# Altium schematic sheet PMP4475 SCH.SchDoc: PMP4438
size A4; VersionControl_RevNumber: A; Date: 2012-12-10; ApprovedBy: Xiaoguang Yu; CheckedBy: David Ji; Author: David Ji; CompanyName: Texas Instruments; DrawnBy: David Ji; Engineer: David Ji; Organization: Power Reference Design; Address1: Texas Instruments; Address2: Power Reference Design; Address3: PMP4438; Address4: Not shown in title block; DocumentNumber: 1; Revision: Rev. A; SheetNumber: 1; SheetTotal: 1; PageSetup: Record=PageOptions¦CenterHorizontal=True¦CenterVertical=True¦PrintScale=0.97¦XCorrection=1.00¦YCorrection=1.00¦PrintKind=0¦BorderSize=5000000¦LeftOffset=0¦BottomOffset=0¦Orientation=2¦PaperLength=1000¦PaperWidth=1000¦Scale=100¦PaperSource=15¦PrintQuality=600¦MediaType=1¦DitherType=10¦PaperKind=Letter¦PrintScaleMode=1
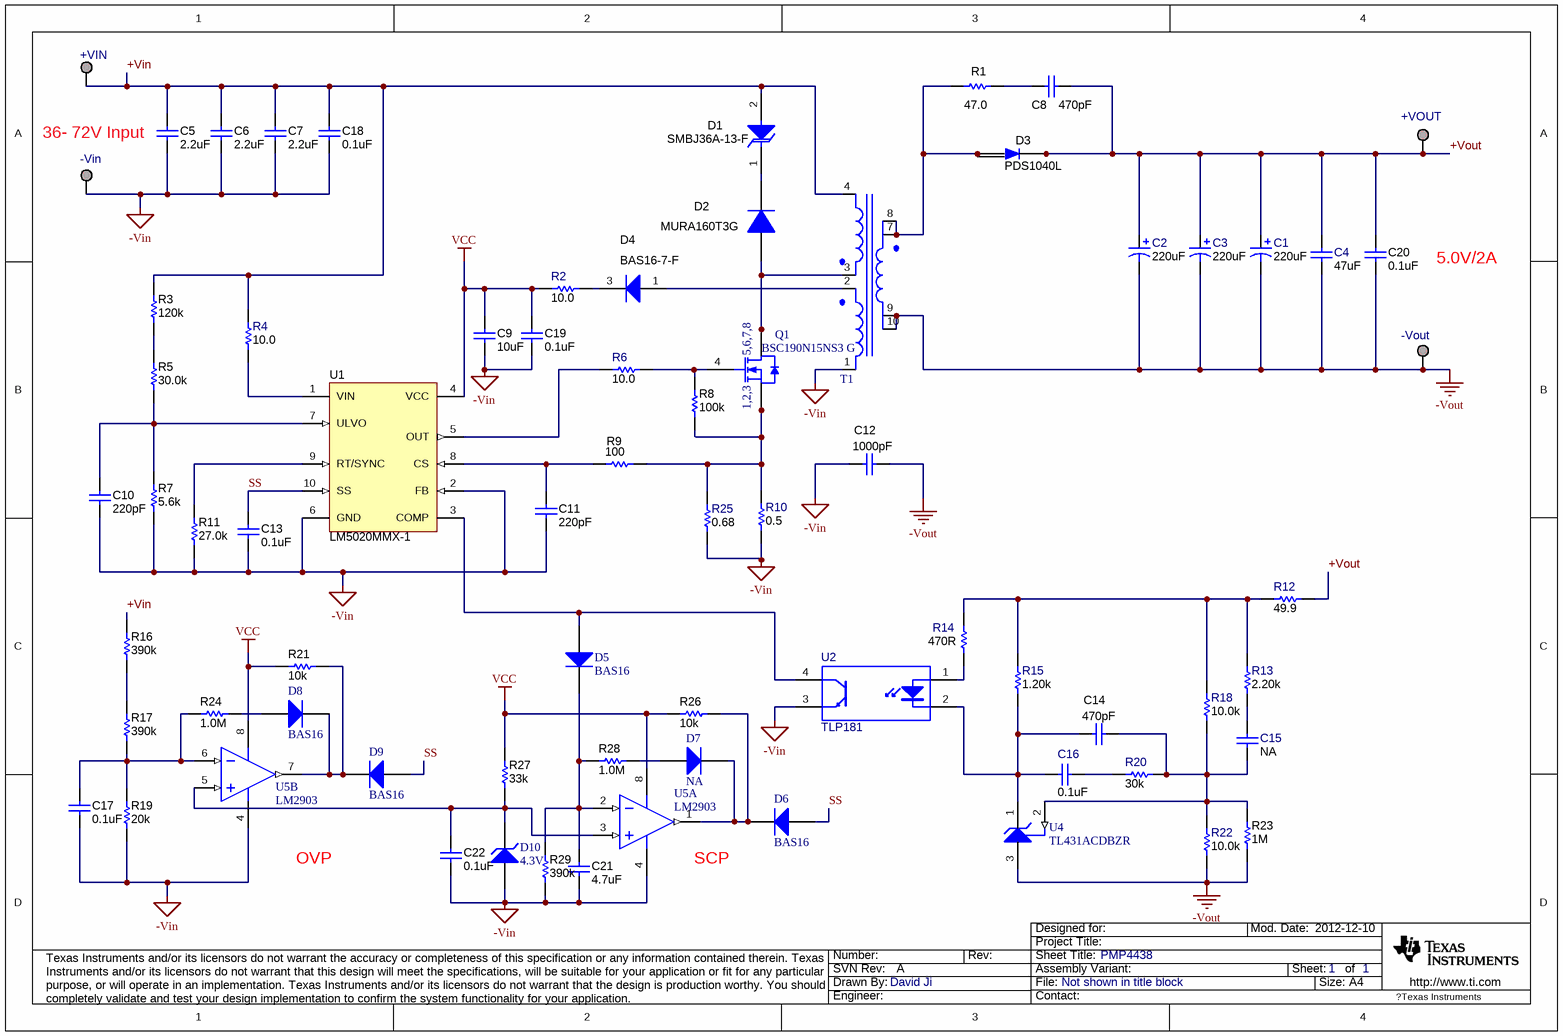
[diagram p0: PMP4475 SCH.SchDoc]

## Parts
+VIN  TESTPOINT  [Copper PIN-1.0]  (value not drawn)  (no BOM)
+VOUT  TESTPOINT  [Copper PIN-1.0]  (value not drawn)  (no BOM)
-Vin  TESTPOINT  [Copper PIN-1.0]  (value not drawn)  (no BOM)
-Vout  TESTPOINT  [Copper PIN-1.0]  (value not drawn)  (no BOM)
C1  ValueDisplayed: 220uF  [POSCAP B2E Size]  (hidden comment: 6TPE150MAPB)
C2  ValueDisplayed: 220uF  [POSCAP B2E Size]  (hidden comment: 6TPE150MAPB)
C3  ValueDisplayed: 220uF  [POSCAP B2E Size]  (hidden comment: 6TPE150MAPB)
C4  ValueDisplayed: 47uF  [1210L]  (hidden comment: GRM32ER61A476KE20L)
C5  ValueDisplayed: 2.2uF  [1206L]  (hidden comment: GRM31CR71H475KA12L)
C6  ValueDisplayed: 2.2uF  [1206L]  (hidden comment: GRM31CR71H475KA12L)
C7  ValueDisplayed: 2.2uF  [1206L]  (hidden comment: GRM31CR71H475KA12L)
C8  ValueDisplayed: 470pF  [0603L]  (hidden comment: GRM1885C1H102JA01D)
C9  ValueDisplayed: 10uF  [0805L]  (hidden comment: GRM21BR71E335KA73L)
C10  ValueDisplayed: 220pF  [0603L]  (hidden comment: GRM188R71E474KA12D)
C11  ValueDisplayed: 220pF  [0603L]  (hidden comment: C0603C101J5GAC)
C12  ValueDisplayed: 1000pF  [2211]  (hidden comment: GRM1885C1H102JA01D)
C13  ValueDisplayed: 0.1uF  [0603L]  (hidden comment: GRM188R71C104KA01D)
C14  ValueDisplayed: 470pF  [0603L]  (hidden comment: GRM1885C1H102JA01D)
C15  ValueDisplayed: NA  [0603L]  (hidden comment: GRM188R71E474KA12D)
C16  ValueDisplayed: 0.1uF  [0603L]  (hidden comment: GRM188R71E474KA12D)
C17  ValueDisplayed: 0.1uF  [0603L]  (hidden comment: GRM188R71C104KA01D)
C18  ValueDisplayed: 0.1uF  [0603L]  (hidden comment: GRM188R71C104KA01D)
C19  ValueDisplayed: 0.1uF  [0603L]  (hidden comment: GRM188R71C104KA01D)
C20  ValueDisplayed: 0.1uF  [0603L]  (hidden comment: GRM188R71C104KA01D)
C21  ValueDisplayed: 4.7uF  [0603L]  (hidden comment: GRM188R71C104KA01D)
C22  0.1uF  [0603L]
D1  SMBJ36A-13-F  [SMB]
D2  MURA160T3G  [SMA]
D3  PDS1040L  [POWERDI-5]
D4  BAS16-7-F  [SOD-323F]
D5  BAS16  [SOD-323F]
D6  BAS16  [SOD-323F]
D7  NA  [SOD-323F]
D8  BAS16  [SOD-323F]
D9  BAS16  [SOD-323F]
D10  4.3V  [SOD-123]
Q1  BSC190N15NS3 G  [SO-8L]
R1  value 47.0  [1206L]  (hidden comment: RC1206FR-0747RL)
R2  value 10.0  [0805L]  (hidden comment: CRCW080510R0FKEA)
R3  value 120k  [0603L]  (hidden comment: RC0603FR-07120KL)
R4  value 10.0  [0805L]  (hidden comment: CRCW080510R0FKEA)
R5  value 30.0k  [0603L]  (hidden comment: RC0603FR-0730KL)
R6  value 10.0  [0805L]  (hidden comment: RC0805FR-072R2L)
R7  value 5.6k  [0603L]  (hidden comment: CRCW060310K0FKEA)
R8  value 100k  [0603L]  (hidden comment: RT0603DRE07100KL)
R9  value 100  [0603L]  (hidden comment: RC0603JR-071KL)
R10  value 0.5  [1210L]  (hidden comment: RC0805FR-072R2L)
R11  value 27.0k  [0603L]  (hidden comment: RC0603FR-0727KL)
R12  value 49.9  [0805L]  (hidden comment: CRCW080549R9FKEA)
R13  value 2.20k  [0603L]  (hidden comment: RC0603FR-072K2L)
R14  value 470R  [0603L]  (hidden comment: RC0603FR-071K2L)
R15  value 1.20k  [0603L]  (hidden comment: RC0603FR-071K2L)
R16  value 390k  [0603L]  (hidden comment: RC0603FR-07120KL)
R17  value 390k  [0603L]  (hidden comment: RC0603FR-07120KL)
R18  value 10.0k  [0603L]  (hidden comment: CRCW060310K0FKEA)
R19  value 20k  [0603L]  (hidden comment: RC0603FR-07120KL)
R20  value 30k  [0603L]  (hidden comment: RC0603FR-071KL)
R21  10k  [0603L]
R22  value 10.0k  [0603L]  (hidden comment: RC0603FR-076K2L)
R23  value 1M  [0603L]  (hidden comment: RC0603FR-07240KL)
R24  1.0M  [0603L]
R25  value 0.68  [1210L]  (hidden comment: RC0805FR-072R2L)
R26  10k  [0603L]
R27  value 33k  [0603L]  (hidden comment: RC0603FR-07120KL)
R28  value 1.0M  [0603L]  (hidden comment: RC0603FR-07120KL)
R29  value 390k  [0603L]  (hidden comment: RC0603FR-07120KL)
T1  Transformer  [WURTH_750313995]  (value not drawn)
U1  LM5020MMX-1  [PCBComponent_1]
U2  TLP181  [TLP181]
U4  TL431ACDBZR  [DBZ0003A_N]
U5  LM2903  [D0008A_N]  (parts A,B of 2)

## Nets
-Vin: -Vin.1 C5.2 C6.2 C7.2 C9.2 C10.2 C11.2 C12.2 C13.2 C17.2 C18.2 C19.2 C21.2 C22.2 D10.1(A) R7.1 R10.2 R11.1 R19.1 R25.2 R29.1 T1.1(Aux-) U1.2(FB) U1.6(GND) U2.3(E) U5.4(VCC-)
-Vout: -Vout.1 C1.2(-) C2.2(-) C3.2(-) C4.2 C12.1 C20.2 R22.1 R23.1 T1.9(Sec-) T1.10(Sec-) U4.3(ANODE)
VCC: C9.1 C19.1 R2.2 R21.2 R26.2 R27.2 U1.4(VCC) U5.8(VCC+)
+Vin: +VIN.1 C5.1 C6.1 C7.1 C18.1 D1.2(A) R3.2 R4.2 R16.2 T1.4(Sec-)
+Vout: +VOUT.1 C1.1(+) C2.1(+) C3.1(+) C4.1 C8.1 C20.1 D3.3 R12.1
SS: C13.1 D6.1(A) D9.1(A) U1.10(SS)
NetC8_2: C8.2 R1.2
NetC10_1: C10.1 R5.1 R7.2 U1.7(ULVO)
NetC11_1: C11.1 R9.2 U1.8(CS)
NetC14_1: C14.1 C15.1 R18.1 R20.1 R22.2 R23.2 U4.2(REF)
NetC14_2: C14.2 C16.1 R15.1 U2.2(K) U4.1(CATHODE)
NetC15_2: C15.2 R13.1
NetC16_2: C16.2 R20.2
NetC17_1: C17.1 R17.1 R19.2 R24.2 U5.6(IN2-)
NetC21_1: C21.1 D5.2(K) R28.2 R29.2 U5.2(IN1-)
NetC22_1: C22.1 D10.2(K) R27.1 U5.3(IN1+) U5.5(IN2+)
NetD1_1: D1.1(K) D2.1(K)
NetD2_2: D2.2(A) Q1.5(D) Q1.6(D) Q1.7(D) Q1.8(D) T1.3(Sec+)
NetD3_1: D3.1 D3.2 R1.1 T1.7(Sec+) T1.8(Sec+)
NetD4_1: D4.1(A) T1.2(Aux+)
NetD4_3: D4.3(K) R2.1
NetD5_1: D5.1(A) U1.3(COMP) U2.4(C)
NetD6_2: D6.2(K) D7.2(K) R26.1 U5.1(OUT1)
NetD7_1: D7.1(A) R28.1
NetD8_1: D8.1(A) R24.1
NetD8_2: D8.2(K) D9.2(K) R21.1 U5.7(OUT2)
NetQ1_1: Q1.1(S) Q1.2(S) Q1.3(S) R8.2 R9.1 R10.1 R25.1
NetQ1_4: Q1.4(G) R6.1 R8.1
NetR3_1: R3.1 R5.2
NetR4_1: R4.1 U1.1(VIN)
NetR6_2: R6.2 U1.5(OUT)
NetR11_2: R11.2 U1.9(RT/SYNC)
NetR12_2: R12.2 R13.2 R14.2 R15.2 R18.2
NetR14_1: R14.1 U2.1(A)
NetR16_1: R16.1 R17.2

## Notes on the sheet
- (near C5) 36- 72V Input
- 5.0V/2A
- (near U5) OVP
- (near U5) SCP

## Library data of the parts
+VIN +VOUT -Vin -Vout = TESTPOINT: TEST POINT.  No entry in BOM.
C1-C3 = APXA6R3ARA151MH70G: CAP, AL, 150uF, 6.3V, +/-20%, 0.025 ohm, SMD; Manufacturer: Sanyo; Alternate PartNumber: T520B157M006ATE025; Alternate Manufacturer: KEMET; Polarized: Y; CompType: Capacitor; U/M: EA; Cap_F: 0.00015; Tolerance_%: 20; VDC_V: 6.3; ESR_Ohm: 0.025; IRMS_A: 2.4; TaMin_C: -40; TaMax_C: 125; Cap_Case: H70
C4 = GRM32ER61A476KE20L: CAP, CERM, 47uF, 10V, +/-10%, X5R, 1210; Manufacturer: MuRata; Polarized: N; CompType: Capacitor; U/M: EA; Cap_F: 0.000047; Tolerance_%: 10; ESR_Ohm: 0.001; Value1: 0.001 ohm; TaMin_C: -55; TaMax_C: 85; Cap_Case: 1210
C5-C7 = GRM31CR71H475KA12L: CAP, CERM, 4.7uF, 50V, +/-10%, X7R, 1206; Manufacturer: MuRata; Polarized: N; CompType: Capacitor; U/M: EA; Cap_F: 0.0000047; Tolerance_%: 10; Value1: Unknown; VDC_V: 50; TaMin_C: -55; TaMax_C: 125; Cap_Case: 2220
C8 C12 C14 = GRM1885C1H102JA01D: CAP, CERM, 1000pF, 50V, +/-5%, C0G/NP0, 0603; Manufacturer: MuRata; Polarized: N; CompType: Capacitor; U/M: EA; Cap_F: 0.000000001; Tolerance_%: 5; Value1: Unknown; VDC_V: 50; TaMin_C: -55; TaMax_C: 125; Cap_Case: 0603
C9 = GRM21BR71E335KA73L: CAP, CERM, 3.3uF, 25V, +/-10%, X7R, 0805; Manufacturer: MuRata; Polarized: N; CompType: Capacitor; U/M: EA; Cap_F: 0.0000033; Tolerance_%: 10; Value1: Unknown; VDC_V: 25; TaMin_C: -55; TaMax_C: 125; Cap_Case: 0805
C10 C15 C16 = GRM188R71E474KA12D: CAP, CERM, 0.47uF, 25V, +/-10%, X7R, 0603; Manufacturer: MuRata; Polarized: N; CompType: Capacitor; U/M: EA; Cap_F: 0.00000047; Tolerance_%: 10; Value1: Unknown; VDC_V: 25; TaMin_C: -55; TaMax_C: 125; Cap_Case: 0603
C11 = C0603C101J5GAC: CAP, CERM, 100pF, 50V, +/-5%, C0G/NP0, 0603; Manufacturer: Kemet; Polarized: N; CompType: Capacitor; U/M: EA; Cap_F: 0.0000000001; Tolerance_%: 5; Value1: Unknown; VDC_V: 50; TaMin_C: -55; TaMax_C: 125; Cap_Case: 0603
C13 C17-C22 = GRM188R71C104KA01D: CAP, CERM, 0.1uF, 16V, +/-10%, X7R, 0603; Manufacturer: MuRata; Polarized: N; CompType: Capacitor; U/M: EA; Cap_F: 0.0000001; Tolerance_%: 10; Value1: Unknown; VDC_V: 16; TaMin_C: -55; TaMax_C: 125; Cap_Case: 0603
D1 = SMBJ36A-13-F: Diode, TVS, Uni, 36V, 600W, SMB; Manufacturer: Diodes Inc.; U/M: EA; Power_W: 5; Vr_V: 36; Value1: 5W
D2 = MURA160T3G: Diode, Ultrafast, 600V, 1A, SMA; Manufacturer: ON Semiconductor; Value: 1.05V; U/M: EA; Vf_V: 1.05; Io_A: 1; Vr_V: 600; TJmax_C: 175
D3 = Diode: Manufacturer: Used in BOM report; SymbolVersion: use current date i.e. 2008-05-20; SymbolCreator: Use a-id; CompType: Used in some BOM reports.  Useful for finding later.; U/M: EA, IN, or GM
D4 = BAS16-7-F: Diode, Ultrafast, 75V, 0.3A, SOT-23; Manufacturer: Diodes Inc.; Value: 1.125V; U/M: EA; Vf_V: 1.125; Io_A: 0.3; Vr_V: 75
D5-D9 = Diode: Default Diode
D10 = D Zener: Zener Diode
Q1 = N-MOSFET
R1 = RC1206FR-0747RL: RES, 47.0 ohm, 1%, 0.25W, 1206; Manufacturer: Yageo America; CompType: Resistor; Res_ohm: 47; Value_Code: 47R0; Tolerance_%: 1; Power_W: 0.25; VDC_V: 200; TempCo: 100 ppm/C; U/M: EA
R2 R4 = CRCW080510R0FKEA: RES, 10.0 ohm, 1%, 0.125W, 0805; Manufacturer: Vishay-Dale; Alternate Manufacturer: Any; Alternate PartNumber: Equivalent; CompType: Resistor; Res_ohm: 10; Value_Code: 10R0; Tolerance_%: 1; Power_W: 0.125; VDC_V: 150; TempCo: 100 ppm/C; EIA_Code: E96; U/M: EA
R3 = RC0603FR-07120KL: RES, 120k ohm, 1%, 0.1W, 0603; Manufacturer: Yageo America; CompType: Resistor; Res_ohm: 120000; Tolerance_%: 1; Power_W: 0.1; VDC_V: 150; TempCo: 200 ppm/C; U/M: EA
R5 = RC0603FR-0730KL: RES, 30.0k ohm, 1%, 0.1W, 0603; Manufacturer: Yageo America; CompType: Resistor; Res_ohm: 30000; Value_Code: 30k0; Tolerance_%: 1; Power_W: 0.1; VDC_V: 150; TempCo: 200 ppm/C; U/M: EA
R6 R10 R25 = RC0805FR-072R2L: RES, 2.20 ohm, 1%, 0.125W, 0805; Manufacturer: Yageo America; CompType: Resistor; Res_ohm: 2.2; Value_Code: 2R20; Tolerance_%: 1; Power_W: 0.125; VDC_V: 150; TempCo: 200 ppm/C; U/M: EA
R7 R18 = CRCW060310K0FKEA: RES, 10.0k ohm, 1%, 0.1W, 0603; Manufacturer: Vishay-Dale; Alternate Manufacturer: Any; Alternate PartNumber: Equivalent; CompType: Resistor; Res_ohm: 10000; Value_Code: 10k0; Tolerance_%: 1; Power_W: 0.1; VDC_V: 75; TempCo: 100 ppm/C; EIA_Code: E96; U/M: EA
R8 = RT0603DRE07100KL: RES, 100k ohm, 0.5%, 0.1W, 0603; Manufacturer: Yageo America; Alternate Manufacturer: Any; Alternate PartNumber: Equivalent; CompType: Resistor; Res_ohm: 100000; Tolerance_%: 0.5; Power_W: 0.1; VDC_V: 75; TempCo: 50 ppm/C; EIA_Code: E192; U/M: EA
R9 = RC0603JR-071KL: RES, 1.0k ohm, 5%, 0.1W, 0603; Manufacturer: Yageo America; CompType: Resistor; Res_ohm: 1000; Value_Code: 1k00; Tolerance_%: 5; Power_W: 0.1; VDC_V: 50; TempCo: 100 ppm/C; EIA_Code: E24; U/M: EA
R11 = RC0603FR-0727KL: RES, 27.0k ohm, 1%, 0.1W, 0603; Manufacturer: Yageo America; CompType: Resistor; Res_ohm: 27000; Value_Code: 27k0; Tolerance_%: 1; Power_W: 0.1; VDC_V: 150; TempCo: 200 ppm/C; U/M: EA
R12 = CRCW080549R9FKEA: RES, 49.9 ohm, 1%, 0.125W, 0805; Manufacturer: Vishay-Dale; CompType: Resistor; Value_Code: 49R9; Tolerance_%: 1; Power_W: 0.125; VDC_V: 150; TempCo: 100 ppm/C; EIA_Code: E96; U/M: EA
R13 = RC0603FR-072K2L: RES, 2.20k ohm, 1%, 0.1W, 0603; Manufacturer: Yageo America; CompType: Resistor; Res_ohm: 2200; Value_Code: 2k20; Tolerance_%: 1; Power_W: 0.1; VDC_V: 150; TempCo: 200 ppm/C; U/M: EA
R14 R15 = RC0603FR-071K2L: RES, 1.20k ohm, 1%, 0.1W, 0603; Manufacturer: Yageo America; Alternate Manufacturer: Any; Alternate PartNumber: Equivalent; CompType: Resistor; Res_ohm: 1200; Value_Code: 1k20; Tolerance_%: 1; Power_W: 0.1; VDC_V: 150; TempCo: 200 ppm/C; U/M: EA
R16 R17 R19 R21 R24 R26-R29 = RC0603FR-07120KL: RES, 10k ohm, 1%, 0.1W, 0603; Manufacturer: Yageo America; CompType: Resistor; Res_ohm: 120000; Value_Code: 120k; Tolerance_%: 1; Power_W: 0.1; VDC_V: 150; TempCo: 200 ppm/C; U/M: EA
R20 = RC0603FR-071KL: RES, 1.00k ohm, 1%, 0.1W, 0603; Manufacturer: Yageo America; CompType: Resistor; Res_ohm: 1000; Value_Code: 1k00; Tolerance_%: 1; Power_W: 0.1; VDC_V: 150; TempCo: 200 ppm/C; EIA_Code: E96; U/M: EA
R22 = RC0603FR-076K2L: RES, 6.20k ohm, 1%, 0.1W, 0603; Manufacturer: Yageo America; CompType: Resistor; Res_ohm: 6200; Value_Code: 6k20; Tolerance_%: 1; Power_W: 0.1; VDC_V: 150; TempCo: 200 ppm/C; U/M: EA
R23 = RC0603FR-07240KL: RES, 240k ohm, 1%, 0.1W, 0603; Manufacturer: Yageo America; Alternate Manufacturer: Any; Alternate PartNumber: Equivalent; CompType: Resistor; Res_ohm: 240000; Tolerance_%: 1; Power_W: 0.1; VDC_V: 150; TempCo: 200 ppm/C; U/M: EA
U1 = LM5020MMX-1: 100V Current Mode PWM Controller, 10-pin MSOP; Manufacturer: National Semiconductor; PackageTopMarking: ZXTT*SBLB; PowerWise: Y; CompType: Switcher
U2 = PS2811-1-M-A: Low Input Current, Hight CTR Photocoupler; Manufacturer: California Eastern Laboratories; SymbolCreator: codlsc; CompType: OPTOCOUPLER; U/M: EA
U4 = TL431ACDBZR: Adjustable Precision Shunt Regulator, 34 ppm / degC, 100 mA, 0 to 70 degC, 3-pin SOT-23 (DBZ), Green (RoHS & no Sb/Br); Manufacturer: Texas Instruments; Alternate Manufacturer: None; Alternate PartNumber: Equivalent; Initial Accuracy @ 25/deg C(%): 1; Iout/Iz(Max)(mA): 100; Min Iz for Regulation(uA): 600; Rating: Catalog; SubFamily: Shunt Voltage Reference; Temp Coeff(Typ)(ppm/ degree C): 34; VO Adj(Max)(V): 36; VO Adj(Min)(V): 2.495
U5 = TL082ACD: JFET-Input Operational Amplifier, 7 to 36 V, 0 to 70 degC, 8-pin SOIC (D0008A), Green (RoHS & no Sb/Br); Alternate Manufacturer: None; Alternate PartNumber: Equivalent; Manufacturer: Texas Instruments; CMRR(Min)(dB): 75; GBW(Typ)(MHz): 3; IIB(Max)(pA): 200; Iq per channel(Max)(mA): 2.8; Number of Channels: 2; Offset Drift(Typ)(uV/C): 18; Rating: Catalog; Slew Rate(Typ)(V/us): 13; Sub Family: General Purpose Amplifier, High Supply Voltage Amplifier (>=30V); Total Supply Voltage(Max)(+5V is 5, +/-5V is 10): 36; Total Supply Voltage(Min)(+5V is 5, +/-5V is 10): 7; Vio (25C)(Max)(mV): 6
